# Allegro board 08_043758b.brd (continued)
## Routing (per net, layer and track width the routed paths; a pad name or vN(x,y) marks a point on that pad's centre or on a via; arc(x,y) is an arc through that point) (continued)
PGND: length 16.2
  TOP w0.203: v1(107.71,111.82) 107.71,111.06 U9.C1 ; U8.C1 110.15,124.57 v1(109.73,124.15)
  TOP w0.254: 111.13,115.27 U16.B2 111.51,114.88
  TOP w0.305: v1(112.42,105) 112.67,105.25 P2.5 ; 110.55,121.12 R69.2 109.99,120.56
  TOP w0.406: P3.5 v1(112.4,123.03)
  TOP w0.635: C171.2 110.94,114.56 ; C171.2 110.3,113.87 ; C171.2 110.94,113.17 ; 110.94,111.39 C172.2 ; C172.2 110.3,112.09 ; C172.2 110.94,112.79
  TOP w0.762: R55.2 115,115.59 ; 110.94,117.99 R58.2 ; R58.2 110.94,119.9 ; R58.2 110.04,118.95
  BOTTOM w0.305: v1(110.24,117.68) 110,117.92 R67.2
  BOTTOM w0.508: Q2.2 110.52,114.12 v1(109.48,114.12)
  vias: v1(110.24,120.22) v1(110.37,112.98) v1(110.37,111.2) v1(110.49,129.11) v1(110.49,128.47) v1(110.49,127.84) v1(111,121.1) v1(111,120.22) v1(111,117.68) v1(111.13,129.11) v1(111.13,128.47) v1(111.13,127.84) v1(111.13,112.98) v1(111.13,111.2) v1(111.76,129.11) v1(111.76,128.47) v1(111.76,127.84) v1(114.56,116.66) v1(114.56,115.9) v1(115.45,116.66) v1(115.45,115.9)
VCCPINT: length 38.6
  TOP w0.305: 85.73,86.56 UNK1P0V.1 ; UNK1P0V.1 86.49,85.8 ; UNK1P0V.1 86.49,87.32 ; UNK1P0V.1 87.25,86.56 ; U4.G10 v2(64.07,103.23) ; U4.K5 v2(60.87,108.03) ; U4.F9 v2(64.87,104.03) ; U4.H5 v2(63.27,108.03) ; U4.G6 v2(63.27,107.23) ; U4.J10 v2(61.67,103.23) ; U4.E10 v2(65.67,103.23) ; U4.L10 v2(60.07,103.23)
  TOP w0.508: 65.53,94.02 C68.1 64.97,94.58
  TOP w0.762: 88.65,88.77 C20.1 ; C20.1 89.7,89.67 ; C20.1 87.6,89.67 ; 92.68,89.67 C21.1 ; C21.1 93.73,88.77 ; C21.1 94.78,89.67 ; 86.11,88.77 C19.1 87.16,89.67 ; 91.19,88.77 C17.1 ; C17.1 90.14,89.67 ; C17.1 92.24,89.67 ; 69.18,94.37 C64.1 ; C64.1 71.7,94.37 ; C64.1 70.44,95.43 ; C71.1 68.44,94.43 ; C71.1 67.19,95.49 ; C71.1 65.93,94.43
  TOP w1.524: 93.54,85.93 L4.2 94.53,88.02
  BOTTOM w0.305: R7.2 92.57,88.34 v1(91.06,88.34)
  BOTTOM w0.406: C66.1 62.37,102.52 v2(61.67,103.23) ; C73.1 60.87,108.03 v2(60.87,108.03) ; C72.1 60.07,103.73 v2(60.07,103.23) ; v2(63.27,108.03) 63.27,108.03 v2(63.27,107.23) 63.27,107.23 C70.1 ; C75.1 64.87,104.64 v2(64.87,104.03) 64.77,103.93 64.27,103.93 C74.1 64.07,103.73 v2(64.07,103.23)
  vias: v1(65.74,94.75) v1(65.74,93.99) v1(68.79,94.75) v1(68.79,93.99) v1(71.96,94.75) v1(71.96,93.99) v1(86.49,88.34) v1(86.49,87.58) v1(87.25,88.34) v1(87.25,87.58) v1(88.01,88.34) v1(88.01,87.58) v1(88.78,88.34) v1(88.78,87.58) v1(89.54,88.34) v1(89.54,87.58) v1(90.3,88.34) v1(90.3,87.58) v1(91.06,87.58)
VCCPLL: length 18.1
  TOP w0.305: U4.F5 v2(64.87,108.03)
  BOTTOM w0.152: 65.27,107.64 64.88,108.03 v2(64.87,108.03) 64.87,108.03 65.27,108.44 66.86,108.44 67.27,108.03 66.88,107.64 65.27,107.64
  BOTTOM w0.508: 71.28,109.33 70.98,109.63 70.28,109.63 69.68,109.03 69.68,108.63 69.17,108.13 68.08,108.13 C178.1 67.27,108.03
  BOTTOM w0.635: 71.28,109.33 73.82,109.33 C85.1 74.43,109.43 76.08,109.43 76.73,108.78 E1.2
VDD33_USB: length 3
  TOP w0.305: v1(88.9,97.23) 88.27,97.23 88.14,97.36 U15.20
  BOTTOM w0.508: v1(88.9,97.23) 88.4,96.72 C165.1
VDD_INTERFACE: length 10.1
  TOP w0.305: C33.1 40.83,87.96 C32.1 ; C33.1 41.24,88.97 ; C33.1 40.83,89.43 ; U5.H12 37.28,99.11 v2(37.37,99.03) C43.1 37.37,97.03 C45.1
  TOP w0.635: 41.6,87.83 C32.1 40.96,87.13 ; E4.2 42.68,85.99 ; E4.2 40.9,85.99 ; E4.2 41.79,86.81
  BOTTOM w0.305: C38.1 37.37,98.53 v2(37.37,99.03) 37.37,99.14 37.37,99.14 C44.1
  vias: v1(41.53,88.72) v1(41.91,87.83) v1(41.91,87.2) v1(42.17,88.72) v1(42.55,87.83) v1(42.55,87.2) v1(42.8,88.72)
VDDA1P1_RX_VCO: length 3.1
  TOP w0.305: U5.G3 v2(37.68,107.16) ; U5.G2 v2(37.68,107.96)
  BOTTOM w0.305: v2(37.69,107.16) C125.2 38.17,107.82 R51.2 38.27,107.96 v2(37.68,107.96)
VIN: length 47.7
  TOP w0.203: 45.49,123.76 U14.10 44.85,124.11
  TOP w0.305: 99.34,113 U6.26 ; v1(74.93,85.1) R80.1 ; 101.98,91.04 R1.2 ; R1.2 102.44,91.45 ; R1.2 101.53,91.45 ; C62.2 45.28,123.34 ; C62.2 44.87,122.88 ; C62.2 45.28,122.42 ; U6.15 99.34,119.3 ; v1(105.54,120.34) 105.35,120.15 R56.1 ; 100.16,88.02 C8.1 99.7,88.43 ; 99.73,90.48 U3.12 99.3,89.73 ; 98.32,118.92 98.52,118.72 98.72,118.72 U6.16 98.84,119.3 ; v1(99.57,112.6) 99.84,112.86 U6.27 ; U15.21 v1(88.4,97.86) 89.34,97.86 C164.1 ; 98.84,113 U6.25 98.75,113.61 98.56,113.61 98.3,113.36 ; 99.84,119.44 U6.14 ; 100.29,91.05 U3.13 101.04,91.48 ; v1(73.17,88.52) 73.35,88.34 C167.1 73.18,87.73 U11.8 ; v1(74.93,86.62) R81.1
  TOP w0.508: C169.1 59.97,84.53 ; C169.1 59.42,85.11 ; C169.1 59.42,83.94 ; DS2.A v1(115.45,82.79) ; DS1.A v1(115.32,91.18)
  TOP w0.635: C9.1 101.92,88.27 ; C9.1 101.22,88.91 ; C9.1 100.52,88.27
  TOP w0.762: C157.1 93.59,130.88 ; C157.1 91.08,130.88 ; C157.1 92.33,129.83 ; C138.1 98.49,123.2 ; C138.1 99.13,122.5 ; C138.1 98.49,121.8 ; 60.46,85.48 E2.1 61.34,84.65 ; C137.1 98.75,110.5 ; C137.1 99.38,109.8 ; C137.1 98.75,109.1 ; 94.2,130.96 Q3.2 95.15,130.2 ; C136.1 98.49,121.42 ; C136.1 99.13,120.72 ; C136.1 98.49,120.02 ; C135.1 98.75,112.28 ; C135.1 98.75,110.88 ; C135.1 99.38,111.58
  TOP w1.016: 103.51,89.43 C11.1 102.45,88.53
  BOTTOM w0.305: v1(44.33,122.88) R221.1 R222.1 ; R6.1 v1(101.48,89.99)
  BOTTOM w0.406: R85.1 98.7,110.82 v1(99.57,110.82) ; R59.2 100.96,110.82 v1(100.21,110.82)
  vias: v1(44.33,122.12) v1(44.96,122.12) v1(60.58,84.4) v1(60.58,83.64) v1(61.47,84.4) v1(61.47,83.64) v1(88.78,131.39) v1(88.78,130.76) v1(88.78,130.12) v1(89.41,131.39) v1(89.41,130.76) v1(89.41,130.12) v1(90.05,131.39) v1(90.05,130.76) v1(90.05,130.12) v1(90.68,131.39) v1(90.68,130.76) v1(90.68,130.12) v1(98.94,124.03) v1(98.94,123.39) v1(98.94,108.91) v1(98.94,108.28) v1(99.32,122.76) v1(99.32,122.12) v1(99.32,121.49) v1(99.57,124.03) v1(99.57,123.39) v1(99.57,110.18) v1(99.57,109.55) v1(99.57,108.91) v1(99.57,108.28) v1(99.57,89.35) v1(99.57,88.72) v1(99.95,122.76) v1(99.95,122.12) v1(99.95,121.49) v1(100.21,124.03) v1(100.21,123.39) v1(100.21,110.18) v1(100.21,109.55) v1(100.21,108.91) v1(100.21,108.28) v1(100.21,89.35) v1(100.21,88.72) v1(100.84,89.99) v1(100.84,89.35) v1(101.48,89.35) v1(102.11,89.99) v1(102.11,89.35) v1(102.75,89.99) v1(103.38,89.99)
VIN_5V_USB: length 3.7
  TOP w0.254: v1(109.73,125.68) 109.83,125.57 U8.A1 ; 108.33,111.32 U9.B1 U9.A1 ; U8.A1 110.44,126.01 ; U8.A1 U8.B1 110.06,125.07 ; U9.A1 108.83,111.32 ; U9.A1 109.22,110.94
  vias: v1(108.46,111.83) v1(108.59,113.1) v1(108.59,112.47) v1(109.1,126.31) v1(109.1,125.68) v1(109.1,125.04) v1(109.1,111.83) v1(109.22,113.1) v1(109.22,112.47) v1(109.73,126.31) v1(109.73,125.04) v1(110.49,132.79) v1(110.49,132.15) v1(110.49,131.52) v1(110.49,130.88) v1(111.13,132.79) v1(111.13,132.15) v1(111.13,131.52) v1(111.13,130.88)
VIN_5V_USB_DATA: length 9.8
  TOP w0.203: R70.1 106.8,109.93 108.33,109.93 108.45,109.81
  TOP w0.254: 108.83,110.06 U9.A2 ; U9.A2 109.22,110.44 ; U9.A2 U9.B2 108.33,109.93
  TOP w0.406: v1(109.1,109.17) 111.07,109.17 112.38,107.85 P2.1
  BOTTOM w0.508: 110.77,109.57 F1.2 110.23,110.18
  vias: v1(108.46,109.8) v1(108.46,109.17) v1(109.1,109.8)
VIN_5V_USB_POWER: length 8.1
  TOP w0.203: R68.1 111.5,124.01 111.76,124.28 111.76,125.04
  TOP w0.254: U8.A2 110.94,125.95 ; U8.A2 111.32,125.57 ; U8.A2 U8.B2 111.32,125.07 ; 112.01,116.15 U16.A1 112.4,115.77
  TOP w0.406: P3.1 112.4,125.63
  L5_SIG w0.635: v1(111.65,125.33) v1(111.65,126.09)
  BOTTOM w0.305: v1(113.03,116.66) 113.02,116.67 R66.1
  vias: v1(113.03,115.9)
1P3_SUPPLY_A: length 71.7
  TOP w0.203: 50.11,86.44 50.23,86.56 50.6,86.56 50.76,86.39 U7.9
  TOP w0.305: U7.11 U7.10 50.11,86.44 ; U7.11 U7.12 ; U7.11 49.46,86.44 ; U5.F2 v2(39.28,107.96) ; U7.12 48.81,86.44 ; U7.12 48.38,85.67 ; C16.1 49.23,88.02 ; C16.1 48.31,88.02 ; C16.1 48.77,87.61 ; U5.B10 v2(42.48,100.76) ; U5.J3 v2(36.09,107.16) ; U7.13 U7.14 47.11,84.09 ; U7.13 47.89,85.17 ; U7.13 47.11,84.74 ; 49.58,88.02 C18.1 ; C18.1 50.04,87.61 ; C18.1 50.5,88.02 ; U5.K3 v2(35.28,107.16) ; U5.B9 v2(42.48,101.56) ; 50.93,88.21 UNK1P3V_A.1 51.69,87.45 ; U5.E2 v2(40.08,107.96)
  TOP w0.635: 46.42,85.48 C15.1 ; C15.1 46.42,86.88 ; C15.1 47.06,86.18 ; 46.55,87.89 C14.1 ; C14.1 47.25,87.26 ; C14.1 47.95,87.89
  BOTTOM w0.305: 40,107.96 v2(39.28,107.96) ; 40,107.96 39.87,108.09 C23.1 39.87,108.84 40.38,109.36 C28.1 ; 40,107.96 v2(40.08,107.96) ; v2(35.28,107.16) 35.03,107.41 35.03,107.52 C24.1 34.8,108.45 C29.1 ; v2(42.48,101.56) 42.4,101.48 C40.1 42.4,100.84 v2(42.48,100.76) ; v2(36.09,107.16) 35.87,107.38 C39.1 35.87,108.34 35.99,108.46
  BOTTOM w0.406: C35.1 42.49,100.76 v2(42.48,100.76)
  BOTTOM w0.508: v1(40.38,118.75) v1(40.38,117.95) C28.1 ; C29.1 33.04,108.77 32.01,109.8 32.01,110.82 32.9,111.71 32.9,116.55 v1(33.28,116.93) v1(33.28,117.74) ; v1(37.21,118.82) v1(37.21,118.06) 35.99,116.83 C34.1 35.99,108.46
  BOTTOM w0.635: C35.1 46.13,100.76 47.25,99.64 47.25,92.16 v1(47.25,92.15) v1(46.39,92.15)
  vias: v1(46.36,87.96) v1(46.36,87.07) v1(47.25,87.07) v1(47.37,86.18) v1(48.14,87.96) v1(48.14,87.07) v1(49.41,87.96) v1(50.68,87.96)
1P3_SUPPLY_B: length 107.7
  TOP w0.203: 28.64,86.56 29.01,86.56 29.17,86.39 U1.9
  TOP w0.305: U1.11 U1.10 28.52,86.44 ; U1.11 U1.12 ; U1.11 27.87,86.44 ; U5.A8 v2(42.48,103.16) ; 26.72,88.02 C5.1 ; C5.1 27.64,88.02 ; C5.1 27.18,87.61 ; 30.23,87.19 UNK1P3V_B.1 29.47,87.96 ; 27.99,88.02 C6.1 ; C6.1 28.45,87.61 ; C6.1 28.91,88.02 ; U5.A7 v2(43.28,103.16) ; U1.12 26.79,85.67 ; U1.12 27.22,86.44 ; U5.M9 v2(33.68,101.56) ; U5.E3 v2(40.08,107.16) ; U5.B8 v2(42.48,102.36) ; U1.13 U1.14 25.52,84.09 ; U1.13 26.3,85.17 ; U1.13 25.52,84.74 ; U5.A10 v2(43.28,101.56) ; U5.F12 v2(39.28,99.16) ; U5.D2 v2(40.88,107.96) ; U5.D3 v2(40.88,107.16) ; U5.A9 v2(43.28,102.36) ; U5.M10 v2(33.68,100.76) ; U5.K4 v2(35.28,106.36)
  TOP w0.635: 24.96,87.89 C4.1 ; C4.1 26.36,87.89 ; C4.1 25.66,87.26 ; 24.83,85.48 C3.1 ; C3.1 25.47,86.18 ; C3.1 24.83,86.88 ; v1(29.68,99.51) 30.71,99.51 L8.1 ; L9.1 v1(29.68,104.97)
  BOTTOM w0.305: v2(39.28,99.16) 39.27,99.14 C26.1 39.27,97.83 C30.1 ; C130.1 28.52,98.18 29.28,98.94 C129.2 29.72,99.47 v1(29.68,99.51) ; v2(35.28,106.36) 34.99,106.06 34.55,106.06 C41.1 34.22,105.72 C36.1 ; v2(42.48,103.16) 42.4,103.08 C27.1 42.4,102.44 v2(42.48,102.36)
  BOTTOM w0.406: 40.88,107.25 41.01,107.38 C42.1 42.37,107.38 C37.1 ; 40.88,107.25 v2(40.88,107.96) ; 40.88,107.25 v2(40.88,107.16) v2(40.08,107.16) ; v2(43.28,103.16) 43.28,103.16 v2(43.28,102.36) ; v2(43.28,103.16) 43.29,103.16 44.03,103.16 ; v2(43.28,103.16) v2(42.48,103.16) ; v2(43.28,102.36) 43.69,102.36 43.95,102.62 43.95,103.08 44.03,103.16 ; v2(43.28,102.36) 43.28,101.56 v2(43.28,101.56) ; v2(43.28,102.36) 43.28,102.36 v2(42.48,102.36) ; 44.03,103.16 C31.1
  BOTTOM w0.508: v1(41.78,115.07) v1(41.78,114.27) 41.78,111.27 44.04,109.01 44.04,107.61 43.68,107.25 C37.1 ; C36.1 32.5,106.25 25.27,106.25 v1(23.45,108.06) v1(22.63,108.06) ; v2(33.68,101.56) 33.68,101.56 v2(33.68,100.76) 32.44,99.51 v1(29.68,99.51) v1(29.68,104.97) ; C31.1 44.84,103.21 45.29,103.66 45.29,109.56 43.09,111.77 v1(43.09,114.27) v1(43.09,115.07)
  BOTTOM w0.635: C30.1 39.44,95.51 38.48,94.56 32.39,94.56 v1(30.36,92.53) v1(29.59,92.53) ; v1(22.63,98.38) v1(23.45,98.38) 23.65,98.18 C130.1 ; E3.2 v1(42.17,128.85)
  vias: v1(24.77,87.96) v1(24.77,87.07) v1(25.66,87.07) v1(25.78,86.18) v1(26.55,87.96) v1(26.55,87.07) v1(27.82,87.96) v1(29.09,87.96)
1P8V_CLK: length 11.9
  TOP w0.305: Y3.4 33.6,89.55 C122.1 33.6,86.46 C121.1 33.91,86.09 v1(33.91,85.16) ; 56.15,87.59 U12.1 56.83,88 ; 53.6,87.45 UNK1P8V_CLK.1 54.36,88.21
  TOP w0.508: C170.1 55.71,87.43 ; C170.1 54.54,87.43 ; C170.1 55.12,87.98
  L6_SIG w0.305: UNK1P8V_CLK.1 53.6,88.97 ; UNK1P8V_CLK.1 54.36,88.21 ; UNK1P8V_CLK.1 53.6,87.45 ; UNK1P8V_CLK.1 52.84,88.21
  vias: v1(54.74,88.21) v1(55.5,88.21)
AD9363_AUXADC: length 49.2
  TOP w0.127: U5.L5 v2(34.49,104.76)
  L6_SIG w0.127: ADC.1 51.18,138.88 44.58,138.88 44.07,138.38 44.07,135.2 38.39,129.52 38.39,122.17 39.09,121.47 39.09,111.66 36.49,109.06 36.49,106.16 36.31,105.98 35.81,105.98 35.68,105.86 35.68,105.36 35.48,105.16 U5.L5 v2(34.49,104.76)
AD9363_AUXDAC1: length 39.8
  TOP w0.127: U5.B3 42.49,106.96 42.69,107.16 43.79,107.16 44.09,107.46 44.09,110.67 45.16,111.74 v1(45.16,113.04)
  L6_SIG w0.127: v1(45.16,113.04) 45.16,115.14 42.45,117.84 42.45,119.74 39.45,122.75 39.45,129.56 42.93,133.04 45.85,133.04 46.46,133.65 46.46,135.99 DAC1.1
AD9363_AUXDAC2: length 35.1
  TOP w0.127: U5.C3 41.69,107.16 42.28,107.16 42.49,107.36 42.49,108.76 43.79,110.06 43.79,110.87 44.46,111.54 v1(44.46,114.04)
  L6_SIG w0.127: DAC2.1 43.95,134.57 39.05,129.67 39.05,122.55 42.05,119.54 42.05,117.74 44.46,115.34 v1(44.46,114.04)
AD9363_GPO_0: length 45.7
  TOP w0.127: U5.B7 42.48,103.96 44.19,103.96 45.29,105.06 45.29,109.77 47.56,112.04 v1(47.56,113.04)
  L6_SIG w0.127: GPO0.1 49.89,131.49 43.41,131.49 41.05,129.13 41.05,123.55 44.06,120.54 44.06,118.24 47.56,114.74 v1(47.56,113.04)
AD9363_GPO_1: length 43
  TOP w0.127: U5.B6 42.48,104.76 43.99,104.76 44.99,105.76 44.99,110.07 46.96,112.04 v1(46.96,114.04)
  L6_SIG w0.127: v1(46.96,114.04) 46.96,114.84 43.66,118.14 43.66,120.34 40.65,123.35 40.65,129.24 43.3,131.89 48.89,131.89 50.42,133.42 GPO1.1
AD9363_GPO_2: length 39.8
  TOP w0.127: v1(46.36,113.04) 46.36,111.94 44.69,110.27 44.69,106.36 43.89,105.56 42.48,105.56 U5.B5
  L6_SIG w0.127: GPO2.1 47.88,133.42 46.75,132.29 43.2,132.29 40.25,129.35 40.25,123.15 43.26,120.14 43.26,118.04 46.36,114.94 v1(46.36,113.04)
AD9363_GPO_3: length 40.9
  TOP w0.127: U5.B4 42.48,106.36 43.69,106.36 44.39,107.06 44.39,110.47 45.76,111.84 v1(45.76,114.04)
  L6_SIG w0.127: GPO3.1 46.76,135.98 46.76,133.44 46.01,132.69 43.09,132.69 39.85,129.46 39.85,122.95 42.85,119.94 42.85,117.94 45.76,115.04 v1(45.76,114.04)
ADM1177_SCL: length 61
  TOP w0.127: v1(82.43,86.94) 81.58,86.09 75.33,86.09 75.23,85.99 73.8,85.99 R81.2 72.72,87.08 U11.7
  L5_SIG w0.127: v1(82.43,86.94) 82.43,87.6 85.49,90.66 85.49,91.68 87.16,93.35 87.16,99.02 86.65,99.53 86.65,104.15 93.32,110.81 93.32,127.58 94.25,128.51 v1(94.9,128.51)
  BOTTOM w0.127: v1(94.9,128.51) 94.9,129.2 94.67,129.43 U10.6
ADM1177_SDA: length 64.7
  TOP w0.127: v1(83.32,87.58) 83.32,86.94 82.08,85.71 73.78,85.71 R80.2 72.52,85.75 72.52,86.18 72.28,86.43 U11.6
  L5_SIG w0.127: v1(96.14,128.51) 95.51,127.87 94.12,127.87 93.68,127.43 93.68,110.66 87.01,104 87.01,99.68 87.52,99.17 87.52,93.2 85.87,91.55 85.87,90.41 84.09,88.63 84.09,88.35 v1(83.32,87.58)
  BOTTOM w0.127: U10.7 95.57,129.93 96.14,129.36 v1(96.14,128.51)
ADP2114_VIN: length 20
  TOP w0.203: 102.11,112.85 101.84,113.12 U6.31
  TOP w0.305: v1(103.89,116.02) 103.77,115.9 U6.4 ; v1(103.25,112.47) 102.49,112.47 102.11,112.85 ; U6.8 103.75,117.9 C141.1 ; C141.1 104.72,118.87 R56.2 104.72,120.15 v1(104.52,120.34) ; C141.1 103.78,119.45 102.14,119.45 101.84,119.15 U6.10
  L5_SIG w0.305: v1(104.52,120.34) 104.52,116.33 104.22,116.02 v1(103.89,116.02) 103.89,115.64 104.64,114.9 104.64,113.34 103.76,112.47 v1(103.25,112.47)
COMP_1P8V: length 2.8
  TOP w0.305: U6.2 103.74,114.9 v1(103.89,114.75)
  BOTTOM w0.508: C142.2 R60.1 104.02,114.63 v1(103.89,114.75)
COMP_1P35V: length 3.1
  TOP w0.305: C144.1 C143.2 104.64,117.4 U6.7
CTRL_IN0: length 52
  TOP w0.102: U4.F13 v2(64.87,100.83) ; U5.C5 v2(41.68,105.56)
  L6_SIG w0.114: v2(64.87,100.83) 64.87,99.19 65.26,98.79 65.26,97.41 61.9,94.05 38.74,94.05 36.49,96.31 36.49,103.66 37.19,104.36 38.69,104.36 38.88,104.56 38.88,105.76 39.89,106.76 41.89,106.76 42.09,106.56 42.09,105.96 41.69,105.56 v2(41.68,105.56)
CTRL_IN1: length 47.2
  TOP w0.102: U5.C6 v2(41.68,104.76) ; v2(64.87,98.43) 64.87,100.03 64.47,100.42 U4.F14
  L6_SIG w0.114: v2(41.68,104.76) 41.68,104.77 41.29,105.17 41.29,105.76 41.09,105.96 40.29,105.96 39.36,105.03 39.36,104.63 38.65,103.93 38.25,103.93 37.89,103.56 37.38,103.56 37.28,103.46 37.28,102.96 36.89,102.56 36.89,96.54 38.87,94.56 61.81,94.56 64.87,97.62 v2(64.87,98.43)
CTRL_IN2: length 37.7
  TOP w0.102: v2(64.07,99.23) U4.G15 ; U5.D6 v2(40.88,104.76)
  L6_SIG w0.114: v2(40.88,104.76) 40.68,104.76 40.15,104.23 39.76,104.23 38.89,103.36 38.89,102.96 38.69,102.76 38.29,102.76 38.09,102.56 38.09,100.45 38.59,99.95 38.59,98.65 39.79,97.45 39.79,96.65 40.36,96.09 60.73,96.09 62.6,97.95 63.2,97.95 63.5,98.25 63.5,98.66 v2(64.07,99.23)
CTRL_IN3: length 41.3
  TOP w0.102: v2(64.07,98.43) 64.47,98.83 U4.F15 ; U5.D5 v2(40.88,105.56)
  L6_SIG w0.114: v2(64.07,98.43) 64.07,97.63 63.51,97.07 62.52,97.07 61.15,95.7 39.25,95.7 37.79,97.16 37.79,99.55 37.29,100.06 37.29,102.56 37.49,102.76 37.89,102.76 38.09,102.96 38.09,103.36 38.3,103.58 38.71,103.58 39.66,104.53 39.66,104.93 39.88,105.16 U5.D5 v2(40.88,105.56)
DDR3_A0: length 30.1
  TOP w0.165: v2(52.46,112.73) 55.57,112.73 56.97,111.33 57.57,111.33 U4.P1 ; v2(59.76,126.15) 59.76,126.15 U2.N3
  L6_SIG w0.165: v2(52.46,112.73) 51.86,113.33 51.86,113.92 52.06,114.12 52.45,114.12 52.65,114.31 52.65,114.59 52.45,114.79 52.06,114.79 51.86,114.99 51.86,115.26 52.06,115.46 52.45,115.46 52.65,115.66 52.65,115.94 52.45,116.13 52.06,116.13 51.86,116.33 51.86,119.37 55.05,122.55 57.56,122.55 57.95,122.95 57.95,123.75 59.76,125.56 v2(59.76,126.15)
  BOTTOM w0.165: v2(59.76,126.15) 60.16,126.55 60.16,128.04 R16.1
DDR3_A1: length 33.2
  TOP w0.165: U4.N1 57.87,111.83 57.17,111.83 55.47,113.53 v2(52.46,113.53) ; U2.P7 58.37,123.54 v2(56.57,123.54)
  L6_SIG w0.165: v2(56.57,123.54) 54.54,123.54 53.92,122.92 53.64,122.92 53.37,123.19 53.09,123.19 52.89,122.99 52.89,122.71 53.16,122.44 53.16,122.16 52.97,121.96 52.69,121.96 52.42,122.24 52.14,122.24 51.94,122.04 51.94,121.76 52.21,121.49 52.21,121.21 52.01,121.01 51.61,121.01 51.26,120.66 51.26,120.26 51.05,120.05 51.05,112.44 52.15,111.34 52.75,111.34 52.95,111.54 52.95,113.04 v2(52.46,113.53)
  BOTTOM w0.165: v2(56.57,123.54) 55.99,123.54 R22.1
DDR3_A2: length 35.7
  TOP w0.165: v2(58.47,112.83) 59.67,111.63 U4.M1 ; U2.P3 v2(58.96,126.15)
  L5_SIG w0.165: v2(58.47,112.83) 58.07,112.83 57.77,112.53 57.77,112.23 58.47,111.53 58.47,111.23 58.07,110.83 58.07,109.83 57.67,109.43 57.47,109.43 57.27,109.63 57.27,110.63 57.07,110.83 56.77,110.83 56.57,110.63 56.57,109.53 56.41,109.37 56.13,109.37 54.37,111.13 54.37,123.08 57.04,125.76 58.56,125.76 v2(58.96,126.15)
  BOTTOM w0.165: v2(58.96,126.15) 58.56,125.76 57.84,125.76 57.15,126.44 55.99,126.44 R17.1
DDR3_A3: length 31.5
  TOP w0.165: U2.N2 v2(59.76,126.95) ; U4.M4 v2(59.27,108.83)
  L5_SIG w0.165: v2(59.27,108.83) 59.56,108.83 59.67,108.94 59.67,109.85 60.02,110.21 60.02,110.51 59.82,110.72 59.44,110.72 59.27,110.89 59.27,114.63 59.07,114.83 58.47,114.83 58.07,115.23 58.07,116.43 58.25,116.61 58.67,116.61 58.87,116.81 58.87,117.09 58.67,117.29 58.27,117.29 58.07,117.48 58.07,117.76 58.27,117.96 58.67,117.96 58.87,118.16 58.87,118.43 58.67,118.63 58.27,118.63 58.07,118.83 58.07,119.11 58.27,119.31 58.67,119.31 58.87,119.5 58.87,119.94 58.66,120.15 58.46,120.15 58.27,120.34 58.27,121.44 58.58,121.75 59.18,121.75 59.36,121.93 59.36,123.61 59.54,123.8 60.05,123.8 60.23,123.97 60.23,124.46 60.39,124.62 61.13,124.62 61.29,124.78 61.29,125 61.13,125.16 60.39,125.16 60.23,125.32 60.23,125.62 60.39,125.78 61.14,125.78 61.3,125.94 61.3,126.16 61.14,126.32 60.19,126.32 60,126.51 60,126.71 v2(59.76,126.95)
  BOTTOM w0.165: R23.1 59.36,128.04 59.36,127.08 59.48,126.95 v2(59.76,126.95)
DDR3_A4: length 26.7
  TOP w0.165: v2(55.87,110.53) 56.77,109.63 57.67,109.63 U4.P3 ; v2(58.96,122.15) U2.P8
  L6_SIG w0.165: v2(58.96,122.15) 59.37,121.74 59.37,120.16 59.16,119.95 58.36,119.95 54.95,116.55 54.95,113.64 55.25,113.34 57.45,113.34 57.67,113.13 57.67,112.63 57.38,112.34 56.58,112.34 56.35,112.12 56.35,111.54 56.15,111.34 55.25,111.34 55.05,111.14 55.05,110.34 55.26,110.13 55.47,110.13 v2(55.87,110.53)
  BOTTOM w0.165: v2(58.96,122.15) 58.56,122.55 56.18,122.55 R18.1
DDR3_A5: length 24
  TOP w0.165: U2.P2 v2(58.96,126.95) ; v2(57.65,108.84) U4.P4
  L5_SIG w0.165: v2(58.96,126.95) 59.36,126.55 59.36,125.85 59.77,125.44 59.77,124.66 58.97,123.86 58.97,122.76 57.87,121.66 57.87,120.24 57.67,120.04 57.67,115.03 58.27,114.43 58.67,114.43 58.87,114.23 58.87,110.73 58.99,110.61 58.99,110.05 58.87,109.93 58.87,109.93 58.87,109.43 58.67,109.23 58.04,109.23 v2(57.65,108.84)
  BOTTOM w0.165: R24.1 58.56,128.04 58.56,127.08 58.68,126.95 v2(58.96,126.95)
DDR3_A6: length 26.8
  TOP w0.165: U4.P5 57.67,108.03 55.67,108.03 v2(55.26,108.43) ; U2.R8 58.16,121.35 57.35,121.35 v2(56.55,120.55)
  L6_SIG w0.165: v2(55.26,108.43) 53.45,110.24 53.45,110.74 53.75,111.04 53.75,116.14 52.75,117.15 52.75,118.95 53.36,119.56 53.64,119.56 53.91,119.28 54.19,119.28 54.38,119.48 54.38,119.76 54.15,119.99 54.15,120.35 54.55,120.75 54.83,120.75 54.96,120.62 54.96,119.84 55.17,119.64 55.67,119.64 55.87,119.84 55.87,120.14 55.63,120.37 55.63,120.75 55.83,120.95 56.16,120.95 v2(56.55,120.55)
  BOTTOM w0.165: R19.1 57.17,120.05 57.06,120.05 v2(56.55,120.55)
DDR3_A7: length 30.3
  TOP w0.165: U2.R2 v2(58.16,126.95) ; U4.M5 v2(59.27,108.03)
  L5_SIG w0.165: v2(58.16,126.95) 57.85,127.26 57.36,127.26 53.56,123.46 53.56,109.83 54.21,109.18 55.11,109.18 56.27,108.03 57.17,108.03 57.57,107.63 58.87,107.63 v2(59.27,108.03)
  BOTTOM w0.165: R25.1 56.66,127.75 57.17,127.24 57.87,127.24 v2(58.16,126.95)
DDR3_A8: length 24.1
  TOP w0.165: U2.T8 56.95,121.75 v2(56.55,121.35) ; U4.P6 57.67,107.23 55.66,107.23 v2(55.26,107.63)
  L6_SIG w0.165: v2(56.55,121.35) 54.55,121.35 52.35,119.15 52.35,116.95 53.35,115.94 53.35,111.34 53.05,111.04 53.05,109.95 54.96,108.04 v2(55.26,107.63)
  BOTTOM w0.165: R20.1 56.06,120.43 56.06,120.85 v2(56.55,121.35)
DDR3_A9: length 27.7
  TOP w0.165: v2(58.15,126.16) U2.R3 ; U4.N4 v2(58.47,108.83)
  L5_SIG w0.165: v2(58.47,108.83) 57.97,108.33 57.47,108.33 56.87,108.93 55.97,108.93 53.97,110.93 53.97,123.24 56.88,126.16 v2(58.15,126.16)
  BOTTOM w0.165: v2(58.15,126.16) 57.49,126.82 56.41,126.82 R26.1
DDR3_A10: length 39.2
  TOP w0.165: U4.J1 61.67,111.23 v2(61.67,112.23) ; U2.L7 61.75,122.55 v2(61.35,122.95)
  L5_SIG w0.165: v2(61.67,112.23) 62.07,111.83 62.07,108.48 62.22,108.33 62.67,108.33 62.87,108.13 62.87,107.83 62.67,107.63 61.47,107.63 61.27,107.83 61.27,111.83 60.86,112.25 60.86,113.06 61.27,113.47 61.47,113.47 61.67,113.67 61.67,113.95 61.47,114.14 61.27,114.14 61.07,114.34 61.07,114.62 61.27,114.82 61.57,114.82 61.86,115.1 61.86,115.34 61.64,115.55 60.86,115.55 60.67,115.74 60.67,115.94 60.89,116.16 61.64,116.16 61.77,116.29 61.77,117.04 61.57,117.24 61.27,117.24 60.78,116.75 60.46,116.75 60.17,117.03 60.17,117.43 60.37,117.62 60.77,117.62 60.97,117.82 60.97,118.1 60.77,118.3 60.37,118.3 60.17,118.5 60.17,119.14 60.37,119.34 60.67,119.34 60.97,119.04 60.97,119.04 61.97,119.04 62.17,119.24 62.17,119.62 61.97,119.81 61.17,119.81 60.97,120.01 60.97,120.29 61.17,120.49 61.47,120.49 61.67,120.68 61.67,121.48 62.17,121.98 62.17,122.39 62.02,122.54 61.77,122.54 v2(61.35,122.95)
  BOTTOM w0.165: v2(61.35,122.95) 60.76,122.95 60.16,122.35 60.16,120.16 R21.1
DDR3_A11: length 32.7
  TOP w0.165: U2.R7 58.16,122.15 v2(56.56,122.15) ; U4.L2 60.07,110.43 60.07,111.83 58.54,113.36 56.54,113.36 v2(55.97,113.93)
  L5_SIG w0.165: v2(55.97,113.93) 55.97,113.22 55.35,112.6 55.35,111.75 55.67,111.43 56.17,111.43 56.52,111.78 56.52,112.98 56.87,113.33 57.27,113.33 57.47,113.53 57.47,114.63 56.97,115.13 56.27,115.13 56.07,115.34 56.07,115.64 56.26,115.83 57.07,115.83 57.27,116.03 57.27,116.31 57.07,116.51 56.36,116.51 56.17,116.7 56.17,116.98 56.36,117.18 57.07,117.18 57.27,117.38 57.27,117.66 57.07,117.85 56.36,117.85 56.17,118.05 56.17,118.33 56.36,118.53 57.07,118.53 57.27,118.72 57.27,119 57.07,119.2 56.36,119.2 56.17,119.4 56.17,119.84 56.37,120.04 56.77,120.04 56.96,120.23 56.96,120.75 56.76,120.95 56.35,120.95 56.16,121.15 56.16,121.75 v2(56.56,122.15)
  BOTTOM w0.165: v2(56.56,122.15) 55.77,121.37 R27.1
DDR3_A12: length 30.5
  TOP w0.165: U4.M2 59.29,110.41 59.29,111.22 57.68,112.83 v2(56.97,112.83) ; U2.N7 59.76,122.95 v2(59.76,122.95)
  L6_SIG w0.165: v2(59.76,122.95) 59.76,123.33 60.52,124.09 60.52,124.39 60.27,124.64 60.04,124.64 59.07,123.67 59.07,122.94 58.55,122.42 58.55,122.12 58.37,121.94 58.05,121.94 57.85,121.74 57.85,121.46 58.05,121.27 58.37,121.27 58.57,121.07 58.57,120.76 56.25,118.45 53.85,118.45 53.63,118.23 53.63,117.76 53.85,117.55 54.35,117.55 54.55,117.35 54.55,113.14 54.86,112.83 v2(56.97,112.83)
  BOTTOM w0.165: R28.1 59.36,120.17 59.36,122.55 v2(59.76,122.95)
DDR3_A13: length 30.8
  TOP w0.165: U4.K2 60.87,110.43 60.87,111.77 58.77,113.87 v2(58.47,113.87) ; U2.T3 57.36,125.35 v2(57.36,125.35)
  L5_SIG w0.165: v2(58.47,113.87) 57.37,112.76 57.37,112.03 56.37,111.03 55.26,111.03 54.77,111.53 54.77,117.23 55.17,117.63 55.17,118.03 54.77,118.43 54.77,118.71 54.96,118.91 55.17,118.91 55.37,119.11 55.37,119.39 55.17,119.58 54.96,119.58 54.77,119.78 54.77,120.06 54.96,120.26 55.17,120.26 55.37,120.45 55.37,120.73 55.17,120.93 54.96,120.93 54.77,121.13 54.77,121.4 54.96,121.6 55.17,121.6 55.37,121.8 55.37,122.08 55.17,122.28 54.89,122.28 54.77,122.4 54.77,122.94 56.57,124.74 56.74,124.74 v2(57.36,125.35)
  BOTTOM w0.165: v2(57.36,125.35) 56.76,125.95 R34.1
DDR3_A14: length 35.5
  TOP w0.165: v2(56.97,113.93) 57.41,114.37 58.86,114.37 61.27,111.97 U4.K1 ; v2(57.36,122.95) U2.T7
  L5_SIG w0.165: v2(57.36,122.95) 57.77,122.54 57.77,122.14 57.46,121.83 57.28,121.83 57.07,122.04 57.07,122.34 56.67,122.74 56.67,123.04 57.37,123.74 57.62,123.74 58.13,123.24 58.37,123.24 58.57,123.44 58.57,123.75 58.11,124.2 58.11,124.48 58.27,124.64 58.57,124.64 58.77,124.44 59.04,124.44 59.25,124.66 59.25,125.12 59.04,125.33 58.16,125.33 56.78,123.95 56.38,123.95 56.15,123.72 56.15,123.38 55.92,123.15 55.58,123.15 55.37,122.94 55.37,122.74 55.76,122.35 55.76,117.26 55.57,117.07 55.36,117.07 55.17,116.88 55.17,116.6 55.36,116.4 55.57,116.4 55.77,116.2 55.77,115.93 55.57,115.73 55.36,115.73 55.17,115.53 55.17,114.43 55.33,114.27 55.61,114.27 55.97,114.63 56.84,114.63 56.97,114.51 v2(56.97,113.93)
  BOTTOM w0.165: R29.1 56.56,122.95 57,123.39 57.23,123.39 57.36,123.27 v2(57.36,122.95)
DDR3_BA0: length 34
  TOP w0.165: U2.M2 v2(60.56,126.95) ; U4.M6 v2(59.27,107.23)
  L5_SIG w0.165: v2(59.27,107.23) 59.67,107.63 60.27,107.63 60.47,107.82 60.47,110.63 59.67,111.43 59.67,115.12 59.47,115.32 58.67,115.32 58.47,115.52 58.47,115.8 58.67,115.99 59.14,115.99 59.36,116.21 59.36,120.05 59.47,120.16 59.47,121.24 60.16,121.93 60.16,122.4 60.38,122.62 60.38,123.57 60.68,123.87 62.11,123.87 62.41,124.18 62.41,124.63 62.18,124.86 61.93,124.86 61.76,125.03 61.76,129.45 61.56,129.66 61.31,129.66 61.12,129.46 61.12,127.51 v2(60.56,126.95)
  BOTTOM w0.165: R35.1 61.26,127.45 61.06,127.25 60.86,127.25 v2(60.56,126.95)
DDR3_BA1: length 30.4
  TOP w0.165: U4.R1 56.89,110.83 v2(55.88,111.84) ; v2(59.76,122.15) U2.N8
  L6_SIG w0.165: v2(55.88,111.84) 55.88,112.22 55.68,112.41 54.82,112.41 54.65,112.24 54.65,109.64 55.21,109.08 55.59,109.08 55.87,109.35 55.87,109.83 56.77,110.73 56.77,111.45 57.05,111.74 57.65,111.74 58.07,112.16 58.07,114.21 57.87,114.4 55.98,114.4 55.75,114.63 55.75,114.85 55.98,115.08 56.37,115.08 56.54,115.25 56.54,115.56 56.3,115.8 55.88,115.8 55.65,116.02 55.65,116.24 55.88,116.47 56.3,116.47 56.67,116.83 56.67,117.66 58.54,119.53 59.34,119.53 59.76,119.95 v2(59.76,122.15)
  BOTTOM w0.165: v2(59.76,122.15) 59.76,119.77 R30.1
DDR3_BA2: length 28.7
  TOP w0.165: v2(61.86,124.35) 60.96,125.25 U2.M3 ; U4.N6 v2(58.47,107.23)
  L6_SIG w0.165: v2(61.86,124.35) 62.15,124.65 62.36,124.65 62.56,124.45 62.56,124.05 61.75,123.25 61.75,119.92 60.87,119.04 60.87,118.53 60.67,118.33 59.24,118.33 57.97,117.06 57.97,116.03 58.17,115.83 58.47,115.83 58.87,116.23 59.17,116.23 59.86,115.54 59.86,113.14 60.26,112.74 60.26,111.84 59.95,111.54 59.56,111.54 58.87,110.85 58.87,108.67 59.11,108.43 59.51,108.43 59.67,108.27 59.67,107.78 59.52,107.63 58.87,107.63 v2(58.47,107.23)
  BOTTOM w0.165: R36.1 61.08,123.57 v2(61.86,124.35)
DDR3_CAS#: length 28.5
  TOP w0.165: v2(56.75,107.63) U4.R5 ; v2(62.16,125.34) 62.56,125.74 U2.K3
  L6_SIG w0.165: v2(62.16,125.34) 61.36,124.54 61.36,123.62 60.76,123.02 60.76,122.75 61.27,122.24 61.27,120.16 59.86,118.75 59.06,118.75 57.55,117.25 57.55,115.55 57.76,115.34 59.06,115.34 59.37,115.03 59.37,112.06 58.07,110.75 58.07,109.69 57.9,109.52 57.35,109.52 57.19,109.36 57.19,108.31 57.47,108.03 57.84,108.03 57.97,107.9 57.97,107.33 57.7,107.06 57.32,107.06 v2(56.75,107.63)
  BOTTOM w0.165: v2(62.16,125.34) 62.17,125.33 62.17,124.89 62.03,124.75 61.48,124.75 R32.1
DDR3_CK_N: length 32.4
  TOP w0.127: U2.K7 62.56,122.55 v2(62.15,122.95) ; U4.N2 v2(58.47,110.43)
  BOTTOM w0.127: R142.2 62.15,123.54 v2(62.15,122.95) 61.76,122.56 61.76,122.32 61.97,122.11 62.15,122.11 62.48,122.45 62.66,122.45 62.96,122.15 62.96,119.45 63.63,118.78 67.33,118.78 67.68,118.43 67.68,117.94 67.36,117.62 63.39,117.62 62.86,117.09 62.86,116.03 62.6,115.77 60.53,115.77 59.35,116.94 58.46,116.94 57.66,116.14 57.66,115.38 59.49,113.54 59.49,110.83 58.84,110.18 58.72,110.18 v2(58.47,110.43)
DDR3_CK_P: length 31.5
  TOP w0.127: U2.J7 v2(62.96,122.95) ; U4.N3 v2(58.47,109.63)
  BOTTOM w0.127: R142.1 62.96,123.35 v2(62.96,122.95) 62.96,122.55 63.24,122.26 63.24,119.57 63.75,119.06 67.45,119.06 67.96,118.54 67.96,117.82 67.48,117.34 63.51,117.34 63.14,116.97 63.14,115.91 62.72,115.49 60.41,115.49 59.24,116.66 58.57,116.66 57.94,116.03 57.94,115.5 59.77,113.66 59.77,110.72 58.95,109.9 58.74,109.9 v2(58.47,109.63)
DDR3_CKE: length 34.9
  TOP w0.165: U4.L3 v2(60.07,109.63) ; v2(62.16,120.55) U2.K9
  L6_SIG w0.165: v2(62.16,120.55) 62.16,118.12 61.83,117.8 59.53,117.8 59.07,117.34 59.07,117.04 59.27,116.83 59.57,116.83 59.86,117.13 61.47,117.13 61.67,116.93 61.67,116.65 61.47,116.45 60.27,116.45 60.07,116.26 60.07,115.98 60.27,115.78 61.82,115.78 61.97,115.63 61.97,115.26 61.82,115.11 60.84,115.11 60.67,114.94 60.67,114.64 60.87,114.43 61.54,114.43 61.67,114.31 61.67,113.89 61.54,113.76 60.67,113.76 60.47,113.56 60.47,113.28 60.67,113.09 61.07,113.09 61.27,112.89 61.27,112.6 61.07,112.4 60.87,112.4 60.67,112.2 60.67,111.92 60.87,111.73 61.92,111.73 62.18,111.46 62.18,111.08 61.94,110.84 59.56,110.84 59.4,110.68 59.4,110.4 59.57,110.23 61.18,110.23 61.37,110.03 61.95,110.03 62.17,109.81 62.17,109.46 61.94,109.23 U4.L3 v2(60.07,109.63)
  BOTTOM w0.165: v2(62.16,120.55) 62.36,120.35 62.36,119.95 62.17,119.76 R38.1
DDR3_CS#: length 29.4
  TOP w0.165: U2.L2 v2(61.36,126.95) ; v2(52.46,111.83) 54.17,111.83 54.86,111.13 55.91,111.13 57.01,110.03 U4.R2
  L6_SIG w0.165: v2(61.36,126.95) 60.77,126.55 59.55,126.55 59.36,126.36 59.36,125.66 56.65,122.95 54.85,122.95 51.46,119.57 51.46,112.83 v2(52.46,111.83)
  BOTTOM w0.165: R39.1 61.76,128.04 61.76,127.08 61.63,126.95 v2(61.36,126.95)
DDR3_DM0: length 26.5
  TOP w0.165: v2(71.67,110.83) 70.79,111.71 68.55,111.71 U4.B1 ; v2(67.76,124.55) 67.76,123.75 U2.E7
  L6_SIG w0.165: v2(71.67,110.83) 73.07,112.23 73.07,121.44 72.72,121.79 72.44,121.79 72.22,121.57 71.94,121.57 71.74,121.77 71.74,122.05 72.06,122.37 72.06,123.25 71.17,124.15 68.16,124.15 v2(67.76,124.55)
DDR3_DM1: length 23.1
  TOP w0.165: U4.D3 v2(66.47,109.63) ; v2(67.76,125.35) U2.D3
  L5_SIG w0.165: v2(67.76,125.35) 67.06,124.66 67.06,122.93 66.56,122.42 66.56,120.05 64.17,117.66 64.17,114.23 62.77,112.83 62.77,109.43 62.96,109.23 66.07,109.23 v2(66.47,109.63)
DDR3_DQ0: length 28.4
  TOP w0.165: U4.D4 v2(66.47,108.83) ; v2(66.96,126.15) 66.96,126.15 U2.E3
  L6_SIG w0.165: v2(66.96,126.15) 67.35,126.15 67.53,125.97 67.53,125.77 67.31,125.55 67.31,124.3 68.26,123.35 70.46,123.35 71.17,122.64 71.17,121.14 71.57,120.73 71.85,120.73 72.02,120.91 72.3,120.91 72.5,120.71 72.5,120.43 72.33,120.26 72.33,119.98 72.67,119.64 72.67,112.53 71.17,111.03 71.17,109.83 69.77,108.43 66.87,108.43 v2(66.47,108.83)
DDR3_DQ1: length 24.7
  TOP w0.165: U2.F7 65.76,123.35 v2(66.56,124.15) ; U4.A2 70.27,110.03 v2(70.67,110.43)
  L6_SIG w0.165: v2(70.67,110.43) 70.67,111.95 71.26,112.54 71.86,112.54 72.17,112.85 72.17,118.83 72.01,118.99 70.78,118.99 70.61,119.16 70.61,119.49 70.78,119.65 71.31,119.65 71.47,119.82 71.47,120.15 71.31,120.31 70.83,120.31 70.66,120.48 70.66,122.35 70.46,122.55 68.16,122.55 v2(66.56,124.15)
DDR3_DQ2: length 23.2
  TOP w0.165: U4.C4 v2(67.27,108.83) ; U2.F2 v2(65.36,126.95)
  L6_SIG w0.165: v2(65.36,126.95) 64.96,126.55 64.35,126.55 63.36,125.56 63.36,122.16 62.95,121.75 62.95,115.35 63.27,115.03 63.27,113.43 63.67,113.03 63.67,112.53 65.27,110.94 65.27,109.44 65.48,109.23 66.87,109.23 v2(67.27,108.83)
DDR3_DQ3: length 28.4
  TOP w0.165: U2.F8 66.16,122.15 66.16,122.95 v2(66.56,123.35) ; U4.C1 68.57,112.53 v2(70.17,112.53)
  L6_SIG w0.165: v2(66.56,123.35) 66.56,123.25 67.87,121.94 68.87,121.94 69.07,121.74 69.07,120.88 69.23,120.72 69.52,120.72 69.69,120.55 69.69,120.22 69.52,120.06 69.23,120.06 69.07,119.89 69.07,119.34 69.89,118.51 71.47,118.51 71.67,118.31 71.67,118.01 71.43,117.77 70.19,117.77 69.96,117.55 69.96,117.24 70.16,117.04 71.51,117.04 71.68,116.88 71.68,116.55 71.51,116.38 70.74,116.38 70.57,116.21 70.57,115.88 70.74,115.72 71.51,115.72 71.68,115.55 71.68,115.22 71.51,115.06 70.94,115.06 70.77,114.89 70.77,114.56 70.94,114.4 71.51,114.4 71.68,114.23 71.68,113.9 71.51,113.74 70.94,113.74 70.77,113.57 70.77,113.13 v2(70.17,112.53)
DDR3_DQ4: length 21.8
  TOP w0.165: U2.H3 64.16,125.75 v2(65.37,124.54) ; v2(68.07,108.83) U4.B4
  L6_SIG w0.165: v2(65.37,124.54) 65.97,124.54 66.16,124.35 66.16,123.05 66.56,122.65 66.56,119.45 68.06,117.95 68.06,117.55 68.36,117.25 68.76,117.25 69.07,116.93 69.07,112.03 69.88,111.22 69.88,109.64 69.47,109.23 68.47,109.23 v2(68.07,108.83)
DDR3_DQ5: length 22.8
  TOP w0.165: v2(66.96,119.75) 65.56,119.75 64.56,120.75 64.56,121.35 U2.H8 ; v2(68.87,108.83) U4.A4
  L6_SIG w0.165: v2(68.87,108.83) 69.57,108.83 70.27,109.53 70.27,111.53 69.57,112.23 69.57,112.87 69.73,113.04 70.06,113.04 70.23,113.2 70.23,113.53 70.06,113.7 69.73,113.7 69.57,113.86 69.57,115.82 69.73,115.98 70.06,115.98 70.23,116.15 70.23,116.48 70.06,116.64 69.73,116.64 69.57,116.81 69.57,117.14 69.23,117.48 69.23,117.72 69.46,117.95 69.46,118.18 69.23,118.42 68.99,118.42 68.76,118.18 68.53,118.18 67.56,119.15 67.56,119.35 68.01,119.8 68.01,120.4 67.86,120.55 67.5,120.55 67.36,120.4 67.36,120.15 v2(66.96,119.75)
DDR3_DQ6: length 23.9
  TOP w0.165: U4.C3 v2(67.27,109.63) ; U2.G2 v2(64.56,126.15)
  L6_SIG w0.165: v2(64.56,126.15) 63.77,125.37 63.77,121.97 63.35,121.55 63.35,120.06 63.56,119.85 63.76,119.85 63.95,119.65 63.95,119.26 63.76,119.06 63.55,119.06 63.35,118.87 63.35,118.59 63.55,118.39 63.76,118.39 63.95,118.19 63.95,117.92 63.76,117.72 63.55,117.72 63.35,117.52 63.35,117.24 63.55,117.05 64.16,117.05 64.35,116.85 64.35,116.57 64.16,116.37 63.55,116.37 63.35,116.18 63.35,115.77 63.48,115.64 63.85,115.64 64.17,115.31 64.17,112.73 64.76,112.14 65.66,112.14 66.06,111.74 66.06,111.4 66.07,111.39 66.07,110.14 66.17,110.03 66.87,110.03 v2(67.27,109.63)
DDR3_DQ7: length 21.8
  TOP w0.165: U2.H7 64.16,122.55 v2(65.36,123.75) ; U4.A3 v2(68.88,109.63)
  L6_SIG w0.165: v2(65.36,123.75) 65.76,123.35 65.76,122.76 66.06,122.45 66.06,121.25 65.76,120.95 65.76,120.1 65.63,119.97 65.48,119.97 65.26,119.75 65.26,119.45 65.42,119.29 66.01,119.29 66.27,119.04 66.27,117.94 66.47,117.73 66.65,117.73 66.97,118.05 67.25,118.05 67.45,117.85 67.45,117.58 67.13,117.26 67.13,116.98 68.07,116.04 68.07,114.76 68.27,114.57 68.37,114.57 68.57,114.37 68.57,114.09 68.37,113.89 68.27,113.89 68.07,113.7 68.07,113.42 68.27,113.22 68.37,113.22 68.57,113.02 68.57,112.75 68.37,112.55 68.27,112.55 68.07,112.35 68.07,111.33 69.37,110.03 69.37,109.73 69.27,109.63 v2(68.88,109.63)
DDR3_DQ8: length 28.2
  TOP w0.165: v2(68.56,124.55) 68.16,124.15 68.16,123.35 U2.D7 ; U4.E1 65.27,110.83 65.67,111.23 v2(65.67,111.23)
  L5_SIG w0.165: v2(68.56,124.55) 68.96,124.15 68.96,123.55 69.16,123.35 69.53,123.35 69.77,123.59 69.77,124.26 70.04,124.54 71.17,124.54 71.89,123.82 71.89,123.44 71.46,123.01 71.46,122.75 71.65,122.56 71.98,122.56 72.16,122.75 72.56,122.75 72.76,122.55 72.76,113.74 70.66,111.64 66.08,111.64 v2(65.67,111.23)
DDR3_DQ9: length 25.8
  TOP w0.165: v2(65.67,110.43) U4.D1 ; v2(68.56,125.35) U2.C3
  L5_SIG w0.165: v2(68.56,125.35) 68.97,124.94 70.45,124.94 70.76,125.25 71.06,125.25 73.26,123.05 73.26,122.23 73.16,122.13 73.16,121.77 73.46,121.47 73.46,113.84 70.86,111.24 69.68,111.24 69.17,110.73 68.57,110.73 68.37,110.93 66.17,110.93 v2(65.67,110.43)
DDR3_DQ10: length 28.6
  TOP w0.165: U4.E2 64.87,110.43 64.87,111.23 65.57,111.93 v2(65.57,112.94) ; U2.C8 68.55,122.15 v2(70.16,122.15)
  L5_SIG w0.165: v2(70.16,122.15) 70.66,121.65 70.66,120.55 70.88,120.33 71.78,120.33 71.96,120.15 71.96,118.93 71.76,118.73 71.36,118.73 71.16,118.53 71.16,118.25 71.36,118.06 71.76,118.06 71.96,117.86 71.96,117.58 71.76,117.38 71.56,117.38 71.36,117.19 71.36,116.91 71.88,116.39 71.88,116.06 71,115.19 71,114.81 71.68,114.13 71.68,113.86 71.08,113.27 70.79,113.27 70.56,113.5 70.56,114.41 70.42,114.55 69.86,114.55 69.66,114.35 69.66,113.75 70.06,113.34 70.06,113.12 69.57,112.63 68.98,112.63 68.76,112.84 68.36,112.84 68.15,112.63 67.3,112.63 67.17,112.76 67.17,113.43 66.67,113.93 66.27,113.93 65.87,113.53 65.87,113.24 v2(65.57,112.94)
DDR3_DQ11: length 27
  TOP w0.165: v2(65.67,109.63) U4.E3 ; v2(68.56,126.15) U2.C2
  L5_SIG w0.165: v2(68.56,126.15) 70.86,126.15 73.86,123.15 73.86,113.64 71.05,110.83 69.95,110.83 69.15,110.03 66.07,110.03 v2(65.67,109.63)
DDR3_DQ12: length 29.5
  TOP w0.165: v2(64.87,109.63) U4.F3 ; v2(70.16,122.95) U2.A7
  L5_SIG w0.165: v2(64.87,109.63) 64.87,111.24 66.07,112.44 66.07,112.93 66.27,113.13 66.51,113.13 66.67,112.97 66.67,112.31 66.93,112.04 70.46,112.04 72.36,113.95 72.36,114.44 72.14,114.66 71.86,114.66 71.66,114.86 71.66,115.14 71.86,115.34 72.15,115.34 72.36,115.54 72.36,120.65 72.19,120.82 71.36,120.82 71.16,121.02 71.16,121.3 71.36,121.49 72.14,121.49 72.36,121.72 72.36,121.95 72.13,122.18 70.93,122.18 70.73,122.38 70.73,122.82 71.26,123.35 71.26,123.66 70.77,124.14 70.37,124.14 70.16,123.93 v2(70.16,122.95)
DDR3_DQ13: length 28.8
  TOP w0.165: v2(63.67,114.33) 63.67,111.73 63.57,111.43 63.57,111.13 U4.G1 ; v2(70.16,126.95) U2.A2
  L5_SIG w0.165: v2(63.67,114.33) 63.31,113.97 63.13,113.97 62.76,114.35 62.76,117.45 62.47,117.73 62.47,118.56 62.65,118.75 63.86,118.75 64.15,119.04 64.15,119.35 63.87,119.63 62.88,119.63 62.67,119.84 62.67,122.07 62.96,122.35 63.36,122.35 63.57,122.57 63.57,126.2 63.16,126.62 63.16,126.95 63.56,127.35 69.76,127.35 v2(70.16,126.95)
DDR3_DQ14: length 28.5
  TOP w0.165: U2.B8 69.36,121.35 69.36,120.55 v2(68.56,119.75) ; U4.H1 62.87,112.13 v2(63.27,112.53)
  L5_SIG w0.165: v2(63.27,112.53) 63.27,112.83 65.16,114.72 65.16,115.05 65.36,115.25 65.69,115.25 65.86,115.42 65.86,115.65 65.65,115.86 64.8,115.86 64.57,116.08 64.57,116.4 64.8,116.63 67.06,116.63 67.26,116.83 67.26,117.11 67.01,117.35 65.31,117.35 65.08,117.58 65.08,117.82 65.31,118.05 65.87,118.05 66.07,118.25 66.07,119.05 66.26,119.25 66.56,119.25 66.76,119.05 66.76,118.25 66.96,118.05 67.16,118.05 67.36,118.25 67.36,122.05 67.52,122.21 67.8,122.21 67.96,122.05 67.96,119.58 68.08,119.46 68.26,119.46 v2(68.56,119.75)
DDR3_DQ15: length 31.7
  TOP w0.165: v2(70.16,125.35) U2.A3 ; U4.H2 62.47,110.43 62.47,112.63 63.27,113.43 63.27,114.63 v2(63.67,115.03)
  L5_SIG w0.165: v2(70.16,125.35) U2.A3 68.25,125.75 67.45,126.55 64.18,126.55 63.97,126.34 63.97,124.34 64.96,123.35 65.66,123.35 65.86,123.15 65.86,121.15 65.66,120.95 64.95,120.95 64.07,121.84 63.54,121.84 63.17,121.47 63.17,120.36 63.38,120.15 64.36,120.15 64.96,119.55 64.96,119.15 63.96,118.15 63.36,118.15 63.17,117.96 63.17,115.53 v2(63.67,115.03)
DDR3_DQS0_N: length 24.1
  TOP w0.127: v2(65.36,125.35) 65.36,125.35 U2.G3 ; U4.B2 v2(68.07,110.43)
  L6_SIG w0.14: v2(68.07,110.43) 67.59,110.91 67.59,113.37 67.21,113.75 65.56,113.75 65.37,113.94 65.37,114.21 65.56,114.4 67.21,114.4 67.59,114.77 67.59,115.72 66.9,116.4 66.46,116.4 65.73,115.66 65.49,115.66 65.12,116.03 65.12,116.21 65.84,116.93 65.84,117.47 64.76,118.55 64.76,125.1 65.01,125.35 v2(65.36,125.35)
DDR3_DQS0_P: length 24.6
  TOP w0.127: U2.F3 v2(65.36,126.15) ; U4.C2 v2(67.27,110.43)
  L6_SIG w0.14: v2(67.27,110.43) 67.27,113.24 67.08,113.43 65.43,113.43 65.06,113.81 65.06,114.34 65.43,114.71 67.08,114.71 67.27,114.9 67.27,115.59 66.77,116.08 66.59,116.08 65.86,115.35 65.36,115.35 64.8,115.9 64.8,116.35 65.52,117.07 65.52,117.33 64.44,118.41 64.44,125.23 v2(65.36,126.15)
DDR3_DQS1_N: length 28.1
  TOP w0.127: v2(69.36,122.95) U2.B7 ; U4.F2 v2(64.07,110.43)
  L5_SIG w0.14: v2(64.07,110.43) 63.86,110.64 63.7,110.64 63.59,110.75 63.59,111.52 64.17,112.11 64.17,112.59 66.3,114.71 66.67,114.71 67.84,113.54 68.43,113.54 68.84,113.95 68.84,114.53 67.67,115.71 67.67,115.98 68.04,116.36 68.45,116.36 69.37,115.43 70.34,115.43 70.74,115.83 70.74,117.27 70.25,117.77 69,117.77 68.78,117.99 68.78,118.31 69,118.54 70.45,118.54 70.86,118.95 70.86,119.59 70.4,120.05 69.7,120.05 69.48,120.28 69.48,121.58 68.88,122.19 68.88,122.47 v2(69.36,122.95)
DDR3_DQS1_P: length 27.7
  TOP w0.127: U4.G2 v2(63.27,110.43) ; U2.C7 v2(68.56,122.95)
  L5_SIG w0.14: v2(68.56,122.95) 68.56,122.05 69.16,121.45 69.16,120.15 69.57,119.74 70.26,119.74 70.55,119.46 70.55,119.08 70.32,118.86 68.87,118.86 68.46,118.45 68.46,117.86 68.87,117.45 70.12,117.45 70.43,117.14 70.43,115.96 70.21,115.75 69.5,115.75 68.58,116.67 67.91,116.67 67.35,116.11 67.35,115.58 68.52,114.4 68.52,114.08 68.3,113.85 67.98,113.85 66.8,115.03 66.17,115.03 63.85,112.72 63.85,112.24 63.27,111.66 v2(63.27,110.43)
DDR3_ODT: length 36.8
  TOP w0.165: U2.K1 v2(62.16,127.75) ; U4.K3 v2(60.87,109.63)
  L5_SIG w0.165: v2(62.16,127.75) 62.15,127.76 62.15,128.96 62.44,129.24 66.58,129.24 66.88,128.94 66.88,128.64 66.63,128.39 63.52,128.39 62.56,127.43 62.56,125.04 62.87,124.74 62.87,123.82 62.51,123.47 60.94,123.47 60.74,123.26 60.74,122.67 61.27,122.14 61.27,121.34 60.88,120.95 60.09,120.95 59.86,120.73 59.86,120.35 60.17,120.04 60.17,119.74 59.77,119.34 59.77,116.03 60.67,115.13 60.67,113.74 60.47,113.54 60.27,113.54 60.07,113.34 60.07,112.03 60.27,111.83 60.67,111.83 60.87,111.63 v2(60.87,109.63)
  BOTTOM w0.165: R33.1 62.86,127.48 62.73,127.36 62.55,127.36 v2(62.16,127.75)
DDR3_RAS#: length 28.5
  TOP w0.165: U4.R6 57.27,106.83 v2(56.76,106.83) ; U2.J3 v2(62.96,125.35)
  L6_SIG w0.165: v2(56.76,106.83) 56.26,107.33 56.26,109.64 58.87,112.26 58.87,114.13 58.16,114.84 57.36,114.84 57.07,115.13 57.07,117.46 58.76,119.15 59.56,119.15 60.16,119.75 60.16,123.03 60.96,123.82 60.96,124.85 61.86,125.75 62.56,125.75 v2(62.96,125.35)
  BOTTOM w0.165: v2(62.96,125.35) 62.57,125.74 61.67,125.74 R37.1
DDR3_RST#: length 29
  TOP w0.165: U2.T2 56.56,127.75 v2(56.16,127.75) ; U4.L4 v2(60.07,108.83)
  L5_SIG w0.165: v2(52.86,123.9) 52.86,124.45 56.16,127.75 v2(56.16,127.75)
  BOTTOM w0.165: v2(60.07,108.83) 59.67,108.43 57.39,108.43 53.15,112.67 53.15,114.35 52.86,114.64 v2(52.86,123.9) ; v2(56.16,127.75) 56.16,128.06 R42.1
DDR3_WE#: length 28.9
  TOP w0.165: U4.R3 55.47,109.23 54.85,109.84 54.45,109.84 v2(54.15,110.14) ; U2.L3 v2(62.16,126.15)
  L6_SIG w0.165: v2(54.15,110.14) 54.15,116.85 53.94,117.06 53.45,117.06 53.25,117.25 53.25,118.65 53.45,118.85 54.55,118.85 54.85,119.15 55.25,119.15 55.55,118.85 56.05,118.85 56.95,119.75 56.95,121.45 58.45,122.95 58.45,123.65 60.14,125.34 60.47,125.34 61.57,126.44 61.87,126.44 v2(62.16,126.15)
  BOTTOM w0.165: v2(62.16,126.15) 61.76,126.55 61.2,126.55 61.08,126.43 R31.1
FB0: length 5.9
  TOP w0.305: U3.4 v1(96.65,94.43)
  BOTTOM w0.305: R4.1 94.24,93.01 94.24,94.56 94.89,95.21 R2.2 v1(96.65,94.43)
FB_1P8V: length 13.7
  TOP w0.203: v1(103.25,113.36) 102.91,113.7 U6.32
  BOTTOM w0.203: v1(103.25,113.36) 102.61,113.36 R65.2 96.54,113.24 93.22,109.93 R64.1
FB_1P35V: length 11.7
  TOP w0.305: U6.9 103.16,118.6 v1(103.38,118.82)
  BOTTOM w0.203: R62.2 96.52,120.98 96.9,120.6 102.62,120.6 103.38,119.83 v1(103.38,118.82) 103.38,118.12 R63.1
IO_02_34_AD9361_CLKOUT: length 27.2
  TOP w0.102: U4.P8 57.67,105.63 56.37,105.63 v2(55.97,105.23) ; U5.J6 v2(36.09,104.76)
  L6_SIG w0.114: v2(36.09,104.76) 36.49,105.16 37.09,105.16 37.29,105.36 37.29,105.76 37.49,105.96 37.89,105.96 38.09,106.16 38.09,107.43 39.01,108.36 51.64,108.36 54.27,105.73 55.46,105.73 v2(55.97,105.23)
  BOTTOM w0.102: AD9361_CLKOUT.1 v2(36.09,104.76)
IO_02_34_AD9361_RST: length 31.6
  TOP w0.102: U4.P9 57.67,104.83 56.36,104.83 v2(55.97,104.43) ; U5.K5 v2(35.28,105.56)
  L5_SIG w0.114: v2(55.97,104.43) 56.37,104.83 56.37,105.51 55.88,105.99 54.87,105.99 49.41,111.45 39.75,111.45 38.11,109.81 37.22,109.81 35.68,108.27 35.68,105.96 v2(35.28,105.56)
IO_L01_34_FB_CLK: length 27.3
  TOP w0.102: v2(56.07,102.83) 56.47,103.23 57.67,103.23 U4.P10 ; U5.F10 v2(39.28,100.76)
  L6_SIG w0.114: v2(56.07,102.83) 56.8,102.1 56.8,100.66 56.5,100.36 56.5,99.11 55.94,98.55 55.69,98.55 54.61,97.48 40.9,97.48 39.69,98.69 39.69,100.36 v2(39.28,100.76)
IO_L01_34_RX_D0: length 50
  TOP w0.102: v2(63.27,100.03) U4.H14 ; v2(35.28,99.96) U5.K11
  L5_SIG w0.114: v2(63.27,100.03) 63.27,99.63 63.37,99.53 63.37,95.57 60.07,92.28 48.5,92.28 47.74,93.04 46.1,93.04 45.72,93.42 45.48,93.42 45.34,93.27 45.34,92.55 45.19,92.4 44.99,92.4 44.84,92.55 44.84,93.27 44.7,93.42 44.24,93.42 44.1,93.56 44.1,93.91 43.95,94.05 43.75,94.05 43.6,93.91 43.6,93.56 43.46,93.42 43.25,93.42 43.11,93.56 43.11,93.91 42.96,94.05 42.76,94.05 42.61,93.91 42.61,93.56 42.47,93.42 42.26,93.42 42.12,93.56 42.12,93.91 41.97,94.05 41.77,94.05 41.62,93.91 41.62,93.56 41.48,93.42 41.27,93.42 41.13,93.56 41.13,93.91 40.98,94.05 40.77,94.05 40.63,93.91 40.63,93.56 40.48,93.42 40.28,93.42 40.13,93.56 40.13,93.91 39.99,94.05 39.78,94.05 39.64,93.91 39.64,93.56 39.49,93.42 39.29,93.42 39.14,93.56 39.14,93.91 39,94.05 38.79,94.05 38.65,93.91 38.65,93.56 38.5,93.42 38.23,93.42 35.31,96.34 35.31,96.81 35.16,96.95 34.69,96.95 34.55,97.1 34.55,97.3 34.69,97.45 35.16,97.45 35.31,97.59 35.31,97.86 35.11,98.07 34.57,98.07 34.42,98.21 34.42,98.42 34.57,98.56 34.74,98.56 34.88,98.71 34.88,99.56 v2(35.28,99.96)
IO_L01_34_RX_D1: length 49.9
  TOP w0.102: U5.J12 36.09,99.16 v2(36.08,99.16) ; v2(62.47,100.83) U4.J13
  L5_SIG w0.114: v2(36.08,99.16) 36.08,96.88 37.51,95.45 38.6,95.45 38.74,95.6 38.74,95.94 38.89,96.09 39.09,96.09 39.24,95.94 39.24,95.6 39.38,95.45 39.59,95.45 39.73,95.6 39.73,95.94 39.88,96.09 40.09,96.09 40.23,95.94 40.23,95.6 40.38,95.45 40.58,95.45 40.73,95.6 40.73,95.94 40.87,96.09 41.08,96.09 41.22,95.94 41.22,95.6 41.37,95.45 41.57,95.45 41.72,95.6 41.72,95.94 41.86,96.09 42.07,96.09 42.21,95.94 42.21,95.6 42.36,95.45 42.56,95.45 42.71,95.6 42.71,95.94 42.85,96.09 43.06,96.09 43.2,95.94 43.2,95.6 43.35,95.45 43.55,95.45 43.7,95.6 43.7,95.94 43.84,96.09 44.05,96.09 44.19,95.94 44.19,95.6 44.34,95.45 44.54,95.45 44.69,95.6 44.69,95.94 44.83,96.09 45.04,96.09 45.18,95.94 45.18,95.6 45.33,95.45 45.57,95.45 45.71,95.6 45.71,95.94 45.86,96.09 46.06,96.09 46.21,95.94 46.21,95.22 46.36,95.07 46.6,95.07 47.27,95.74 47.47,95.74 47.62,95.59 47.62,95.39 47.16,94.93 47.16,94.72 47.3,94.58 47.51,94.58 47.97,95.04 48.17,95.04 48.32,94.89 48.32,94.69 47.86,94.23 47.86,94.02 48,93.88 48.21,93.88 48.67,94.33 48.87,94.33 49.02,94.19 49.02,93.98 48.56,93.53 48.56,93.32 48.84,93.04 59.57,93.04 62.07,95.54 62.07,99.63 62.47,100.03 v2(62.47,100.83)
IO_L02_34_RX_D2: length 50.2
  TOP w0.102: v2(64.07,100.03) U4.G14 ; U5.K10 v2(35.28,100.76)
  L5_SIG w0.114: v2(64.07,100.03) 64.47,99.63 64.47,95.4 60.58,91.51 42.42,91.51 42.04,91.89 42.04,92.53 41.91,92.66 41.55,92.66 41.41,92.51 41.41,91.91 41.26,91.77 41.06,91.77 40.91,91.91 40.91,92.51 40.77,92.66 40.56,92.66 40.42,92.51 40.42,91.91 40.27,91.77 40.07,91.77 39.92,91.91 39.92,92.51 39.78,92.66 37.72,92.66 33.4,96.97 33.4,97.61 33.66,97.86 33.66,98.24 33.4,98.5 33.4,98.9 33.66,99.15 33.66,99.4 33.4,99.65 33.4,99.9 34.08,100.57 34.08,100.95 34.28,101.16 34.89,101.16 v2(35.28,100.76)
IO_L02_34_RX_D3: length 49.9
  TOP w0.102: v2(36.08,99.95) U5.J11 ; U4.H13 v2(63.27,100.83)
  L5_SIG w0.114: v2(36.08,99.95) 35.68,99.56 35.68,96.6 37.85,94.43 38.09,94.43 38.24,94.58 38.24,94.92 38.38,95.07 38.59,95.07 38.73,94.92 38.73,94.58 38.88,94.43 39.08,94.43 39.23,94.58 39.23,94.92 39.37,95.07 39.58,95.07 39.72,94.92 39.72,94.58 39.87,94.43 40.07,94.43 40.22,94.58 40.22,94.92 40.36,95.07 40.57,95.07 40.71,94.92 40.71,94.58 40.86,94.43 41.06,94.43 41.21,94.58 41.21,94.92 41.35,95.07 41.56,95.07 41.7,94.92 41.7,94.58 41.85,94.43 42.05,94.43 42.2,94.58 42.2,94.92 42.34,95.07 42.55,95.07 42.69,94.92 42.69,94.58 42.84,94.43 43.04,94.43 43.19,94.58 43.19,94.92 43.33,95.07 43.54,95.07 43.68,94.92 43.68,94.58 43.83,94.43 44.34,94.43 44.48,94.29 44.48,93.94 44.63,93.8 44.83,93.8 44.98,93.94 44.98,94.92 45.12,95.07 45.33,95.07 45.47,94.92 45.47,93.94 45.62,93.8 45.82,93.8 45.97,93.94 45.97,94.29 46.11,94.43 46.99,94.43 47.12,94.31 47.12,94.17 46.78,93.83 46.78,93.63 46.93,93.48 47.13,93.48 47.45,93.8 47.61,93.8 48.76,92.66 59.82,92.66 62.47,95.31 62.47,99.53 62.77,99.83 62.77,100.33 v2(63.27,100.83)
IO_L03_34_RX_D4: length 51.6
  TOP w0.102: U5.K9 v2(35.28,101.56) ; U4.G12 v2(64.07,101.63)
  L5_SIG w0.114: v2(35.28,101.56) 34.89,101.96 33.47,101.96 33.02,101.51 33.02,96.72 38.61,91.13 60.84,91.13 65.27,95.57 65.27,99.23 64.47,100.03 64.47,101.03 64.27,101.23 64.14,101.23 64.07,101.3 v2(64.07,101.63)
IO_L03_34_RX_D5: length 50.6
  TOP w0.102: U4.H12 v2(63.27,101.63) ; U5.J10 v2(36.09,100.76)
  L5_SIG w0.114: v2(63.27,101.63) 63.67,101.23 63.67,95.24 60.33,91.89 48.28,91.89 47.52,92.66 46.1,92.66 45.47,92.02 44.58,92.02 44.45,92.15 44.45,92.91 44.33,93.04 44.06,93.04 43.91,92.89 43.91,92.17 43.77,92.02 43.56,92.02 43.42,92.17 43.42,92.89 43.27,93.04 43.07,93.04 42.92,92.89 42.92,92.17 42.78,92.02 42.57,92.02 42.43,92.17 42.43,92.89 42.28,93.04 37.98,93.04 34.07,96.95 34.07,100.14 34.28,100.35 35.68,100.35 36.08,100.76 v2(36.09,100.76)
IO_L04_34_RX_D6: length 55.4
  TOP w0.102: U4.G11 v2(64.07,102.43) ; U5.K8 v2(35.28,102.36)
  L5_SIG w0.114: v2(35.28,102.36) 34.89,102.76 33.73,102.76 32.64,101.67 32.64,96.47 38.36,90.75 61.09,90.75 66.07,95.73 66.07,99.27 65.81,99.53 65.57,99.53 65.27,99.83 65.27,101.03 65.07,101.23 64.67,101.23 64.47,101.43 64.47,102.03 v2(64.07,102.43)
